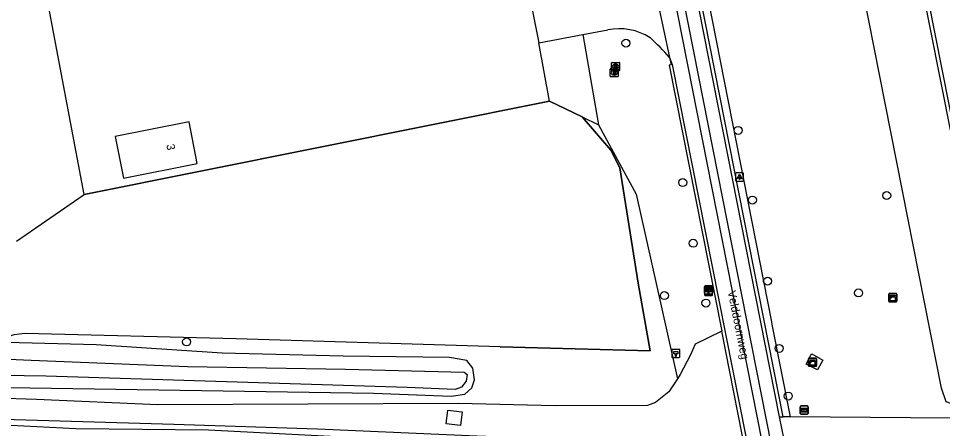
# Model space of a CAD drawing. Extents: x 160203 to 161526, y 379529 to 381797.
# Drawn here: x 160881.8 to 160995.1, y 379661.9 to 379712.2 of the extents above; entities that cross this region are included whole.
import ezdxf

# ---------------------------------------------------------------- set-up
doc = ezdxf.new("R2010")
doc.units = 0
for name, color, linetype in [('IMGEO_Boom', 7, 'Continuous'), ('IMGEO_Brandkraan', 7, 'Continuous'), ('IMGEO_Fietspad_open', 7, 'Continuous'), ('IMGEO_Grasland_overig', 7, 'Continuous'), ('IMGEO_Groenvoorziening', 7, 'Continuous'), ('IMGEO_Hectometerpaal', 7, 'Continuous'), ('IMGEO_Hek', 7, 'Continuous'), ('IMGEO_Kast', 7, 'Continuous'), ('IMGEO_Lichtpunt', 7, 'Continuous'), ('IMGEO_Loofbos', 7, 'Continuous'), ('IMGEO_Openbare_ruimte_label', 7, 'Continuous'), ('IMGEO_Pand', 7, 'Continuous'), ('IMGEO_Pand_nummerreeks', 7, 'Continuous'), ('IMGEO_Rijbaan_lokaal_gesloten', 7, 'Continuous'), ('IMGEO_Rijbaan_lokaal_open', 7, 'Continuous'), ('IMGEO_Voetpad_open', 7, 'Continuous'), ('IMGEO_Wegwijzer', 7, 'Continuous')]:
    doc.layers.add(name, color=color, linetype=linetype)

msp = doc.modelspace()

# ---------------------------------------------------------------- linework, layer by layer
at = {"layer": 'IMGEO_Boom'}
for centre in [(160956.25, 379709.18), (160970.01, 379698.49), (160963.22, 379692.1), (160988.22, 379690.51), (160971.76, 379689.95), (160964.5, 379684.65), (160973.62, 379680.01), (160960.97, 379678.24), (160984.77, 379678.56), (160966.06, 379677.33), (160902.4, 379672.57), (160975.04, 379671.77), (160976.16, 379665.93)]:
    msp.add_circle(centre, 0.489, dxfattribs=at)
at = {"layer": 'IMGEO_Brandkraan'}
for p, q in [((160954.48, 379705.89), (160954.48, 379706.75)), ((160954.56, 379706.82), (160955.41, 379706.82)), ((160955.48, 379706.75), (160955.48, 379705.89)), ((160954.32, 379705.12), (160954.32, 379705.98)), ((160954.39, 379706.05), (160955.25, 379706.05)), ((160955.41, 379705.82), (160954.56, 379705.82)), ((160954.81, 379705.83), (160954.83, 379705.83)), ((160954.97, 379706.6), (160955, 379706.6)), ((160954.99, 379706.04), (160954.97, 379706.04)), ((160955.32, 379705.98), (160955.32, 379705.12)), ((160955.25, 379705.05), (160954.39, 379705.05)), ((160954.83, 379705.27), (160954.8, 379705.27))]:
    msp.add_line(p, q, dxfattribs=at)
for points in [[(160954.48, 379705.89), (160954.48, 379706.75)], [(160954.56, 379706.82), (160955.41, 379706.82)], [(160955.48, 379706.75), (160955.48, 379705.89)], [(160954.32, 379705.12), (160954.32, 379705.98)], [(160954.39, 379706.05), (160955.25, 379706.05)], [(160955.41, 379705.82), (160954.56, 379705.82)], [(160954.67, 379705.75), (160954.67, 379705.35), (160954.88, 379705.35)], [(160954.9, 379705.75), (160954.67, 379705.75)], [(160954.84, 379705.67), (160954.79, 379705.67), (160954.79, 379705.59)], [(160954.79, 379705.59), (160954.84, 379705.59)], [(160954.83, 379706.52), (160954.83, 379706.12), (160955.04, 379706.12)], [(160955.06, 379706.52), (160954.83, 379706.52)], [(160955.01, 379706.44), (160954.96, 379706.44), (160954.96, 379706.36)], [(160954.96, 379706.36), (160955.01, 379706.36)], [(160955.02, 379706.29), (160954.96, 379706.29), (160954.96, 379706.2)], [(160954.96, 379706.2), (160955.02, 379706.2)], [(160955.32, 379705.98), (160955.32, 379705.12)], [(160955.25, 379705.05), (160954.39, 379705.05)], [(160954.85, 379705.52), (160954.79, 379705.52), (160954.79, 379705.44)], [(160954.79, 379705.44), (160954.85, 379705.44)]]:
    msp.add_lwpolyline(points, dxfattribs=at)
for centre, radius, start, end in [((160954.56, 379706.74), 0.0765, 91.552, 178.448), ((160954.56, 379706.74), 0.0765, 91.552, 178.448), ((160955.41, 379706.74), 0.0765, 1.552, 88.448), ((160955.41, 379706.74), 0.0765, 1.552, 88.448), ((160954.39, 379705.98), 0.0765, 91.552, 178.448), ((160954.39, 379705.98), 0.0765, 91.552, 178.448), ((160954.56, 379705.89), 0.0765, 181.552, 268.448), ((160954.56, 379705.89), 0.0765, 181.552, 268.448), ((160954.85, 379705.63), 0.0379, 267.8285, 90.9355), ((160954.9, 379705.61), 0.145, 59.4692, 91.5367), ((160954.93, 379705.65), 0.0922, 285.5137, 58.1501), ((160954.93, 379705.46), 0.105, 301.3115, 78.989), ((160955.01, 379706.4), 0.0379, 267.8285, 90.9355), ((160955.02, 379706.25), 0.0404, 269.8759, 90.5077), ((160955.05, 379706.37), 0.251, 268.6676, 293.5347), ((160955.07, 379706.37), 0.145, 59.4692, 91.5367), ((160955.09, 379706.42), 0.0922, 285.5137, 58.1501), ((160955.1, 379706.23), 0.105, 301.3115, 78.989), ((160955.24, 379705.98), 0.0765, 1.552, 88.448), ((160955.24, 379705.98), 0.0765, 1.552, 88.448), ((160955.41, 379705.89), 0.0765, 271.552, 358.448), ((160955.41, 379705.89), 0.0765, 271.552, 358.448), ((160954.39, 379705.13), 0.0765, 181.552, 268.448), ((160954.39, 379705.13), 0.0765, 181.552, 268.448), ((160954.85, 379705.48), 0.0404, 269.8759, 90.5077), ((160954.88, 379705.6), 0.251, 268.6676, 293.5347), ((160955.24, 379705.13), 0.0765, 271.552, 358.448), ((160955.24, 379705.13), 0.0765, 271.552, 358.448)]:
    msp.add_arc(centre, radius, start, end, dxfattribs=at)
for centre, major_axis, ratio, start_param, end_param in [((160954.81, 379705.55), (-0.387, 0.002), 0.722429, 4.712389, 7.853982), ((160954.97, 379706.32), (-0.387, 0.002), 0.722429, 4.712389, 7.853982), ((160954.83, 379705.55), (-0.39, 0.002), 0.717154, 1.570796, 4.712389), ((160954.99, 379706.32), (-0.39, 0.002), 0.717154, 1.570796, 4.712389)]:
    msp.add_ellipse(centre, major_axis=major_axis, ratio=ratio, start_param=start_param, end_param=end_param, dxfattribs=at)
at = {"layer": 'IMGEO_Fietspad_open'}
for points in [[(160976.37, 379663.39), (160975.52, 379663.39)], [(161063.74, 379662.75), (161006.45, 379663.11), (161000.99, 379663.16), (160976.37, 379663.39)]]:
    msp.add_lwpolyline(points, dxfattribs=at)
at = {"layer": 'IMGEO_Grasland_overig'}
for points in [[(160960.29, 379881.14), (160984.65, 379758.21), (161001.9, 379671.16), (161088.81, 379688.39), (161124.8, 379695.53), (161114.01, 379750)], [(160889.82, 379690.64), (160882.02, 379731.98), (160938.84, 379743.37)], [(160968, 379673.87), (160964.76, 379672.27), (160964.17, 379670.97), (160962.9, 379668.56), (160962.56, 379668.04)], [(160962.56, 379668.04), (160961.52, 379666.45), (160959.86, 379665.14), (160958.91, 379664.75), (160947.59, 379664.74), (160935.67, 379665.03), (160898.81, 379664.84), (160883.98, 379665.5), (160868.89, 379665.98), (160828.06, 379666.96), (160812.93, 379667.08), (160784.17, 379667.9), (160765.94, 379668.23)], [(160965.09, 379656.72), (160964.92, 379656.84), (160962.96, 379657.72), (160959.85, 379658.69), (160953.41, 379659.26), (160941.37, 379660.02), (160925.57, 379660.67), (160905.1, 379661.73), (160888.82, 379661.93), (160879.21, 379662.41), (160871.12, 379662.49), (160848.79, 379663.19), (160828.27, 379664.03), (160812.26, 379664.39), (160788.1, 379664.5), (160775.51, 379664.76), (160761.02, 379665.38), (160747.4, 379665.72), (160736.25, 379666.08), (160724.71, 379666.34)], [(160768.72, 379665.89), (160783.83, 379665.68), (160798.49, 379665.21), (160840.84, 379664.24), (160900.83, 379662.49), (160918.44, 379661.9), (160937.96, 379661.05), (160955.51, 379660.4), (160964.23, 379660.55)]]:
    msp.add_lwpolyline(points, dxfattribs=at)
at = {"layer": 'IMGEO_Groenvoorziening'}
for points in [[(160933.99, 379879.07), (160974.08, 379675.03), (160974.15, 379674.69), (160976.37, 379663.39)], [(160952.89, 379699.18), (160957.49, 379690.67), (160962.56, 379668.04)], [(160754, 379670.17), (160779.34, 379669.05), (160786.69, 379669.13), (160796.33, 379669.07), (160808.49, 379668.46), (160839.92, 379667.95), (160875.27, 379667.07), (160925.29, 379666.27), (160934.84, 379665.92), (160936.5, 379666.16), (160937.38, 379666.93), (160937.67, 379667.93), (160937.49, 379669.34), (160936.75, 379670.28), (160934.64, 379670.66), (160921.57, 379670.82), (160906.77, 379671.18), (160891.29, 379672.2), (160842.51, 379673.48), (160825.19, 379673.58)], [(160766.24, 379673.54), (160782.51, 379673.2), (160792.15, 379672.79), (160822.07, 379671.95), (160865.8, 379671.12), (160883.33, 379670.33), (160902.49, 379669.56), (160921.88, 379669.22), (160936.41, 379668.85), (160936.8, 379668.56), (160936.67, 379667.77), (160936.09, 379667.02), (160935.32, 379666.72)], [(160935.32, 379666.72), (160929.42, 379666.96), (160885.15, 379668.38), (160856, 379668.81), (160800.46, 379670.24), (160787.45, 379670.4), (160779.42, 379670.28), (160758.24, 379671.16)]]:
    msp.add_lwpolyline(points, dxfattribs=at)
at = {"layer": 'IMGEO_Hectometerpaal'}
for p, q in [((160965.88, 379679.17), (160965.88, 379678.33)), ((160965.88, 379679.17), (160965.88, 379678.33)), ((160966.79, 379679.26), (160965.95, 379679.26)), ((160966.79, 379679.26), (160965.95, 379679.26)), ((160966.88, 379678.34), (160966.88, 379679.18)), ((160966.88, 379678.34), (160966.88, 379679.18)), ((160965.96, 379678.26), (160966.8, 379678.26)), ((160965.96, 379678.26), (160966.8, 379678.26)), ((160961.88, 379671.57), (160961.88, 379670.72)), ((160961.88, 379671.57), (160961.88, 379670.72)), ((160962.79, 379671.65), (160961.95, 379671.65)), ((160962.79, 379671.65), (160961.95, 379671.65)), ((160962.88, 379670.73), (160962.88, 379671.58)), ((160962.88, 379670.73), (160962.88, 379671.58)), ((160961.96, 379670.65), (160962.8, 379670.65)), ((160961.96, 379670.65), (160962.8, 379670.65))]:
    msp.add_line(p, q, dxfattribs=at)
for points in [[(160966.4, 379678.4), (160966.34, 379678.4), (160966.34, 379678.71), (160966.12, 379678.71), (160966.12, 379678.98), (160966.62, 379678.98), (160966.62, 379678.71), (160966.4, 379678.71), (160966.4, 379678.4)], [(160962.4, 379670.79), (160962.34, 379670.79), (160962.34, 379671.1), (160962.12, 379671.1), (160962.12, 379671.37), (160962.62, 379671.37), (160962.62, 379671.1), (160962.4, 379671.1), (160962.4, 379670.79)]]:
    msp.add_lwpolyline(points, dxfattribs=at)
for centre, start, end in [((160965.96, 379679.18), 92.4484, 184.2845), ((160965.96, 379679.18), 92.4484, 184.2845), ((160966.8, 379679.18), 2.4484, 94.2845), ((160966.8, 379679.18), 2.4484, 94.2845), ((160965.96, 379678.34), 182.4484, 274.2845), ((160965.96, 379678.34), 182.4484, 274.2845), ((160966.8, 379678.34), 272.4484, 4.2845), ((160966.8, 379678.34), 272.4484, 4.2845), ((160961.96, 379671.57), 92.4484, 184.2845), ((160961.96, 379671.57), 92.4484, 184.2845), ((160962.8, 379671.57), 2.4484, 94.2845), ((160962.8, 379671.57), 2.4484, 94.2845), ((160961.96, 379670.73), 182.4484, 274.2845), ((160961.96, 379670.73), 182.4484, 274.2845), ((160962.8, 379670.73), 272.4484, 4.2845), ((160962.8, 379670.73), 272.4484, 4.2845)]:
    msp.add_arc(centre, 0.0779, start, end, dxfattribs=at)
at = {"layer": 'IMGEO_Hek'}
for points in [[(161000, 379678.61), (160985.83, 379750)], [(160889.82, 379690.64), (160882.02, 379731.98), (160938.84, 379743.37)], [(160944.72, 379713.51), (160945.57, 379709.21)], [(160946.9, 379702.08), (160945.57, 379709.21)], [(160946.9, 379702.08), (160889.82, 379690.64)], [(160950.89, 379700.14), (160946.9, 379702.08)], [(160940.83, 379671.98), (160959.24, 379671.47), (160957.77, 379679.76), (160955.51, 379693.91), (160954.39, 379696.07), (160950.89, 379700.14)], [(160940.83, 379671.98), (160908.47, 379672.95), (160882.6, 379673.6), (160881.21, 379673.45), (160879.82, 379672.97), (160869.97, 379673.11), (160857.9, 379673.43), (160844.53, 379673.94), (160833.38, 379673.96), (160827.65, 379674.08)]]:
    msp.add_lwpolyline(points, dxfattribs=at)
at = {"layer": 'IMGEO_Kast'}
for p, q in [((160988.47, 379677.56), (160988.47, 379678.4)), ((160988.47, 379678.4), (160988.47, 379677.56)), ((160988.54, 379678.49), (160989.38, 379678.49)), ((160989.38, 379678.49), (160988.54, 379678.49)), ((160989.47, 379678.41), (160989.47, 379677.57)), ((160989.47, 379677.57), (160989.47, 379678.41)), ((160989.39, 379677.49), (160988.55, 379677.49)), ((160988.55, 379677.49), (160989.39, 379677.49)), ((160978.62, 379669.66), (160978.62, 379670.5)), ((160978.62, 379670.5), (160978.62, 379669.66)), ((160978.7, 379670.59), (160979.54, 379670.59)), ((160979.54, 379670.59), (160978.7, 379670.59)), ((160979.62, 379670.51), (160979.62, 379669.67)), ((160979.62, 379669.67), (160979.62, 379670.51)), ((160979.55, 379669.59), (160978.71, 379669.59)), ((160978.71, 379669.59), (160979.55, 379669.59))]:
    msp.add_line(p, q, dxfattribs=at)
for points in [[(160988.66, 379678.28), (160989.26, 379678.28), (160989.26, 379678.19), (160988.66, 379678.19), (160988.66, 379678.28)], [(160988.66, 379678.1), (160989.26, 379678.1), (160989.26, 379677.61), (160988.66, 379677.61), (160988.66, 379678.1)], [(160978.82, 379670.38), (160979.42, 379670.38), (160979.42, 379670.29), (160978.82, 379670.29), (160978.82, 379670.38)], [(160978.82, 379670.2), (160979.42, 379670.2), (160979.42, 379669.71), (160978.82, 379669.71), (160978.82, 379670.2)]]:
    msp.add_lwpolyline(points, dxfattribs=at)
for centre in [(160988.75, 379677.95), (160978.9, 379670.05)]:
    msp.add_circle(centre, 0.0377, dxfattribs=at)
for centre, start, end in [((160988.55, 379678.41), 92.4484, 184.2845), ((160988.55, 379678.41), 92.4484, 184.2845), ((160989.39, 379678.41), 2.4484, 94.2845), ((160989.39, 379678.41), 2.4484, 94.2845), ((160988.55, 379677.57), 182.4484, 274.2845), ((160988.55, 379677.57), 182.4484, 274.2845), ((160989.39, 379677.57), 272.4484, 4.2845), ((160989.39, 379677.57), 272.4484, 4.2845), ((160978.7, 379670.51), 92.4484, 184.2845), ((160978.7, 379670.51), 92.4484, 184.2845), ((160979.54, 379670.51), 2.4484, 94.2845), ((160979.54, 379670.51), 2.4484, 94.2845), ((160978.7, 379669.66), 182.4484, 274.2845), ((160978.7, 379669.66), 182.4484, 274.2845), ((160979.54, 379669.66), 272.4484, 4.2845), ((160979.54, 379669.66), 272.4484, 4.2845)]:
    msp.add_arc(centre, 0.0779, start, end, dxfattribs=at)
at = {"layer": 'IMGEO_Lichtpunt'}
for p, q in [((160969.68, 379693.18), (160969.68, 379692.38)), ((160969.68, 379693.18), (160969.68, 379692.38)), ((160970.59, 379693.28), (160969.78, 379693.28)), ((160970.59, 379693.28), (160969.78, 379693.28)), ((160970.68, 379692.38), (160970.68, 379693.18)), ((160970.68, 379692.38), (160970.68, 379693.18)), ((160969.78, 379692.28), (160970.59, 379692.28)), ((160969.78, 379692.28), (160970.59, 379692.28))]:
    msp.add_line(p, q, dxfattribs=at)
for points in [[(160970.06, 379692.85), (160970.1, 379692.82), (160969.91, 379692.56), (160969.87, 379692.58), (160970.06, 379692.85)], [(160970.16, 379692.8), (160970.21, 379692.8), (160970.21, 379692.48), (160970.16, 379692.48), (160970.16, 379692.8)], [(160970.27, 379692.82), (160970.31, 379692.85), (160970.5, 379692.58), (160970.46, 379692.56), (160970.27, 379692.82)]]:
    msp.add_lwpolyline(points, dxfattribs=at)
msp.add_circle((160970.18, 379692.98), 0.0994, dxfattribs=at)
for centre, start, end in [((160969.78, 379693.18), 90, 180), ((160969.78, 379693.18), 90, 180), ((160970.59, 379693.18), 0, 90), ((160970.59, 379693.18), 0, 90), ((160969.78, 379692.38), 180, 270), ((160969.78, 379692.38), 180, 270), ((160970.59, 379692.38), 270, 0), ((160970.59, 379692.38), 270, 360)]:
    msp.add_arc(centre, 0.0946, start, end, dxfattribs=at)
at = {"layer": 'IMGEO_Loofbos'}
for points in [[(161122.82, 379708.52), (161125.46, 379695.28), (161089.34, 379688.04), (161001.69, 379670.67), (161000, 379678.61), (160985.83, 379750), (160984.11, 379758.57), (160973.15, 379813.39), (160960.04, 379879.9), (160959.92, 379880.51)], [(161136.23, 379692.23), (161130.68, 379689.47), (161118.14, 379687.03), (161106.5, 379683.85), (161096.48, 379679.04), (161085.04, 379672.67), (161070.4, 379668.01), (161059.14, 379666.39), (161049.4, 379665.53), (161034.57, 379663.65), (161025.83, 379663.99), (161019.86, 379665.34), (161017.76, 379665.27), (161013.76, 379664.34), (161011.91, 379663.38), (161000.99, 379663.27), (160995.51, 379665.23), (160994.95, 379666.91), (160953.02, 379879)], [(160950.95, 379710.23), (160952.89, 379699.18)], [(160946.9, 379702.08), (160945.57, 379709.21)], [(160889.82, 379690.64), (160946.9, 379702.08)], [(160946.9, 379702.08), (160950.89, 379700.14)], [(160950.89, 379700.14), (160954.39, 379696.07), (160955.51, 379693.91), (160957.77, 379679.76), (160959.24, 379671.47), (160940.83, 379671.98), (160908.47, 379672.95), (160882.6, 379673.6), (160881.21, 379673.45), (160879.82, 379672.97), (160869.97, 379673.11), (160857.9, 379673.43), (160844.53, 379673.94), (160833.38, 379673.96), (160827.65, 379674.08)], [(160950.89, 379700.14), (160952.89, 379699.18)], [(160881.55, 379684.93), (160889.82, 379690.64)]]:
    msp.add_lwpolyline(points, dxfattribs=at)
at = {"layer": 'IMGEO_Pand'}
msp.add_lwpolyline([(160894.67, 379692.62), (160903.71, 379694.42), (160902.69, 379699.55), (160893.65, 379697.75), (160894.67, 379692.62)], dxfattribs=at)
at = {"layer": 'IMGEO_Rijbaan_lokaal_gesloten'}
for points in [[(160975.09, 379663.4), (160924.29, 379920.91), (160923.14, 379926.74)], [(160930.17, 379876.91), (160975.99, 379644.84)], [(160931.19, 379877.16), (160977.01, 379644.98)], [(160958.63, 379721.42), (160961.6, 379707.42)], [(160961.6, 379707.42), (160961.94, 379706.57), (160974.23, 379644.48), (160973.83, 379644.42)], [(160975.92, 379659.23), (160975.09, 379663.4)]]:
    msp.add_lwpolyline(points, dxfattribs=at)
at = {"layer": 'IMGEO_Rijbaan_lokaal_open'}
for points in [[(160975.52, 379663.39), (160933, 379878.98)], [(160944.72, 379713.51), (160945.57, 379709.21)], [(160945.57, 379709.21), (160950.95, 379710.23)], [(160950.95, 379710.23), (160954.03, 379710.81)], [(160961.6, 379707.42), (160961.79, 379706.53), (160961.55, 379706.48), (160968, 379673.87)], [(160971.5, 379656.22), (160968, 379673.87)], [(160975.09, 379663.4), (160975.52, 379663.39)]]:
    msp.add_lwpolyline(points, dxfattribs=at)
for centre, radius, start, end in [((160955.42, 379703.88), 7.07, 57.5977, 101.3115), ((160942.12, 379690.63), 25.72, 40.7712, 48.3733)]:
    msp.add_arc(centre, radius, start, end, dxfattribs=at)
at = {"layer": 'IMGEO_Voetpad_open'}
for points in [[(160980.18, 379669.95), (160979.75, 379669.14), (160978.36, 379669.85), (160978.94, 379670.92), (160979.04, 379671.1), (160980.4, 379670.34), (160980.18, 379669.95)], [(160934.22, 379662.54), (160934.42, 379664.21), (160936.18, 379664), (160935.97, 379662.32), (160934.22, 379662.54)]]:
    msp.add_lwpolyline(points, dxfattribs=at)
at = {"layer": 'IMGEO_Wegwijzer'}
for p, q in [((160965.87, 379678.52), (160965.87, 379679.32)), ((160965.87, 379679.32), (160965.87, 379678.52)), ((160965.97, 379679.42), (160966.76, 379679.42)), ((160966.76, 379679.42), (160965.97, 379679.42)), ((160966.76, 379678.42), (160965.97, 379678.42)), ((160965.97, 379678.42), (160966.76, 379678.42)), ((160966.86, 379679.32), (160966.86, 379678.52)), ((160966.86, 379678.52), (160966.86, 379679.32)), ((160977.61, 379663.81), (160977.61, 379664.61)), ((160977.61, 379664.61), (160977.61, 379663.81)), ((160977.71, 379664.71), (160978.5, 379664.71)), ((160978.5, 379664.71), (160977.71, 379664.71)), ((160978.5, 379663.71), (160977.71, 379663.71)), ((160977.71, 379663.71), (160978.5, 379663.71)), ((160978.6, 379664.61), (160978.6, 379663.81)), ((160978.6, 379663.81), (160978.6, 379664.61))]:
    msp.add_line(p, q, dxfattribs=at)
for points in [[(160965.97, 379679.15), (160966.75, 379679.15), (160966.75, 379678.69), (160965.97, 379678.69), (160965.97, 379679.15)], [(160966.03, 379679), (160966.03, 379678.92), (160966.03, 379678.84), (160966.44, 379678.84), (160966.44, 379678.75), (160966.69, 379678.92), (160966.44, 379679.09), (160966.44, 379679), (160966.03, 379679)], [(160977.71, 379664.44), (160978.5, 379664.44), (160978.5, 379663.97), (160977.71, 379663.97), (160977.71, 379664.44)], [(160977.78, 379664.29), (160977.78, 379664.21), (160977.78, 379664.12), (160978.19, 379664.12), (160978.19, 379664.04), (160978.43, 379664.21), (160978.19, 379664.37), (160978.19, 379664.29), (160977.78, 379664.29)]]:
    msp.add_lwpolyline(points, dxfattribs=at)
for centre, start, end in [((160965.97, 379679.32), 90, 180), ((160965.97, 379679.32), 90, 180), ((160965.97, 379678.52), 180, 270), ((160965.97, 379678.52), 180, 270), ((160966.76, 379679.32), 0, 90), ((160966.76, 379679.32), 360, 90), ((160966.76, 379678.52), 270, 0), ((160966.76, 379678.52), 270, 0), ((160977.71, 379664.61), 90, 180), ((160977.71, 379664.61), 90, 180), ((160977.71, 379663.81), 180, 270), ((160977.71, 379663.81), 180, 270), ((160978.5, 379664.61), 0, 90), ((160978.5, 379664.61), 360, 90), ((160978.5, 379663.81), 270, 0), ((160978.5, 379663.81), 270, 0)]:
    msp.add_arc(centre, 0.1, start, end, dxfattribs=at)

# ---------------------------------------------------------------- texts
at = {"layer": 'IMGEO_Openbare_ruimte_label'}
msp.add_text('Velddoornweg', height=1, rotation=281.2987, dxfattribs=at).set_placement((160968.72, 379678.74))
at = {"layer": 'IMGEO_Pand_nummerreeks'}
msp.add_text('3', height=1, rotation=281.261, dxfattribs=at).set_placement((160899.91, 379696.72))

doc.saveas('drawing.dxf')
